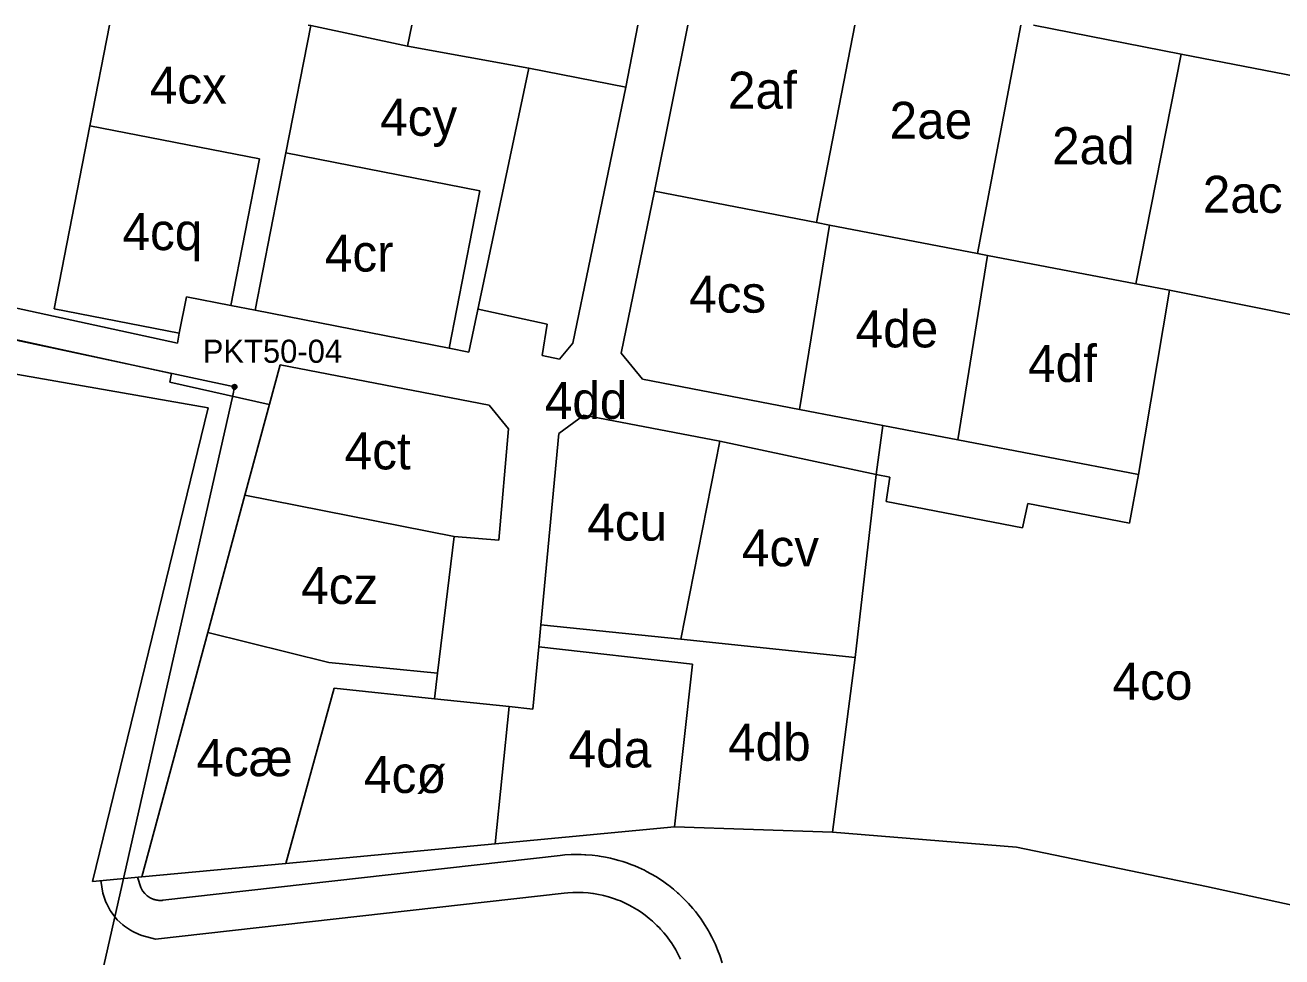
# Model space of a CAD drawing. Extents: x 702630 to 703245, y 6205279 to 6205714.
# Drawn here: x 702766.1 to 702969.7, y 6205559 to 6205710 of the extents above; entities that cross this region are included whole.
import ezdxf

# ---------------------------------------------------------------- set-up
doc = ezdxf.new("R2010")
doc.units = 0
for name, color, linetype in [('Matrikelnummer', 7, 'Continuous'), ('Matrikelnummer punkt', 7, 'Continuous'), ('Matrikelskel Almindeligt', 7, 'Continuous'), ('Matrikelskel Vej', 7, 'Continuous'), ('Optaget vej', 7, 'Continuous'), ('Punkt', 7, 'Continuous'), ('Punkt_Text', 7, 'Continuous'), ('Trykledning', 7, 'Continuous')]:
    doc.layers.add(name, color=color, linetype=linetype)

msp = doc.modelspace()

# ---------------------------------------------------------------- linework, layer by layer
at = {"layer": 'Matrikelnummer punkt'}
for p, q in [((702790.96, 6205700.28), (702790.96, 6205700.28)), ((702884.4, 6205699.46), (702884.4, 6205699.46)), ((702828.34, 6205695.07), (702828.34, 6205695.07)), ((702910.94, 6205694.58), (702910.94, 6205694.58)), ((702937.47, 6205690.46), (702937.47, 6205690.46)), ((702961.65, 6205682.59), (702961.65, 6205682.59)), ((702786.56, 6205676.54), (702786.56, 6205676.54)), ((702818.97, 6205673.07), (702818.97, 6205673.07)), ((702878.18, 6205666.41), (702878.18, 6205666.41)), ((702905.44, 6205660.78), (702905.44, 6205660.78)), ((702933.03, 6205655.18), (702933.03, 6205655.18)), ((702855.27, 6205649.19), (702855.27, 6205649.19)), ((702821.9, 6205641.01), (702821.9, 6205641.01)), ((702861.9, 6205629.48), (702861.9, 6205629.48)), ((702887, 6205625.31), (702887, 6205625.31)), ((702815.37, 6205619.21), (702815.37, 6205619.21)), ((702946.93, 6205603.68), (702946.93, 6205603.68)), ((702884.81, 6205593.8), (702884.81, 6205593.8)), ((702858.94, 6205592.72), (702858.94, 6205592.72)), ((702799.44, 6205591.3), (702799.44, 6205591.3)), ((702825.76, 6205588.58), (702825.76, 6205588.58))]:
    msp.add_line(p, q, dxfattribs=at)
at = {"layer": 'Matrikelskel Almindeligt'}
for p, q in [((702779.79, 6205710), (702776.6, 6205693.68)), ((702808.36, 6205689.31), (702812.39, 6205709.92)), ((702811.96, 6205710), (702812.39, 6205709.92)), ((702812.39, 6205709.92), (702828.07, 6205706.6)), ((702828.07, 6205706.6), (702828.73, 6205710)), ((702900.53, 6205710), (702894.35, 6205678.01)), ((702927.44, 6205710), (702920.44, 6205672.99)), ((702828.07, 6205706.6), (702847.72, 6205703.01)), ((702953.4, 6205705.3), (702946.08, 6205668.07)), ((702847.72, 6205703.01), (702838.02, 6205657.02)), ((702847.72, 6205703.01), (702863.43, 6205699.94)), ((702770.81, 6205664.04), (702776.6, 6205693.68)), ((702776.6, 6205693.68), (702804.09, 6205688.31)), ((702808.36, 6205689.31), (702803.37, 6205663.79)), ((702839.77, 6205683.17), (702808.36, 6205689.31)), ((702804.09, 6205688.31), (702799.45, 6205664.56)), ((702834.78, 6205657.65), (702839.77, 6205683.17)), ((702894.35, 6205678.01), (702868.1, 6205683.08)), ((702896.45, 6205677.61), (702891.6, 6205647.72)), ((702896.45, 6205677.61), (702894.35, 6205678.01)), ((702920.44, 6205672.99), (702896.45, 6205677.61)), ((702922.05, 6205672.68), (702920.44, 6205672.99)), ((702922.05, 6205672.68), (702917.22, 6205642.79)), ((702946.08, 6205668.07), (702922.05, 6205672.68)), ((702951.51, 6205667.04), (702946.08, 6205668.07)), ((702946.52, 6205637.17), (702951.51, 6205667.04)), ((702980.12, 6205661.33), (702951.51, 6205667.04)), ((702770.81, 6205664.04), (702791.08, 6205660.08)), ((702748.87, 6205656.2), (702795.76, 6205648)), ((702801.71, 6205633.81), (702807.42, 6205654.96)), ((702795.76, 6205648), (702777, 6205571.25)), ((702878.66, 6205642.57), (702872.33, 6205610.52)), ((702904, 6205637.18), (702900.62, 6205607.54)), ((702795.7, 6205611.57), (702801.71, 6205633.81)), ((702801.71, 6205633.81), (702835.61, 6205627.16)), ((702872.33, 6205610.52), (702849.66, 6205612.81)), ((702785.01, 6205571.99), (702795.7, 6205611.57)), ((702815.29, 6205606.72), (702795.7, 6205611.57)), ((702900.62, 6205607.54), (702872.33, 6205610.52)), ((702849.33, 6205609.28), (702874.25, 6205606.46)), ((702832.92, 6205604.97), (702815.29, 6205606.72)), ((702874.25, 6205606.46), (702871.34, 6205580.08)), ((702896.93, 6205579.22), (702900.62, 6205607.54)), ((702816.18, 6205602.55), (702808.33, 6205574.16)), ((702832.42, 6205600.84), (702816.18, 6205602.55)), ((702844.53, 6205599.57), (702842.25, 6205577.33)), ((702842.25, 6205577.33), (702871.34, 6205580.08)), ((702871.34, 6205580.08), (702896.93, 6205579.22)), ((702896.93, 6205579.22), (702926.75, 6205576.82)), ((702808.33, 6205574.16), (702842.25, 6205577.33)), ((702926.75, 6205576.82), (702957.55, 6205570.41)), ((702785.01, 6205571.99), (702808.33, 6205574.16)), ((702785.01, 6205571.99), (702777, 6205571.25)), ((702957.55, 6205570.41), (702997.74, 6205561.71))]:
    msp.add_line(p, q, dxfattribs=at)
at = {"layer": 'Matrikelskel Vej'}
for p, q in [((702863.43, 6205699.94), (702865.37, 6205710)), ((702873.48, 6205710), (702868.1, 6205683.08)), ((702929.5, 6205710), (702953.4, 6205705.3)), ((702953.4, 6205705.3), (702972.11, 6205701.65)), ((702868.1, 6205683.08), (702862.66, 6205656.85)), ((702792.23, 6205665.97), (702791.08, 6205660.08)), ((702799.45, 6205664.56), (702792.23, 6205665.97)), ((702799.45, 6205664.56), (702803.37, 6205663.79)), ((702803.37, 6205663.79), (702834.78, 6205657.65)), ((702838.02, 6205657.02), (702834.78, 6205657.65)), ((702862.66, 6205656.85), (702866.15, 6205652.64)), ((702807.42, 6205654.96), (702841.3, 6205648.43)), ((702866.15, 6205652.64), (702891.6, 6205647.72)), ((702841.3, 6205648.43), (702844.41, 6205644.59)), ((702852.55, 6205643.84), (702856.62, 6205646.79)), ((702856.62, 6205646.79), (702878.66, 6205642.57)), ((702891.6, 6205647.72), (702905.06, 6205645.13)), ((702844.41, 6205644.59), (702842.86, 6205626.57)), ((702904, 6205637.18), (702905.06, 6205645.13)), ((702905.06, 6205645.13), (702917.22, 6205642.79)), ((702849.66, 6205612.81), (702852.55, 6205643.84)), ((702878.66, 6205642.57), (702904, 6205637.18)), ((702917.22, 6205642.79), (702946.52, 6205637.17)), ((702835.61, 6205627.16), (702832.92, 6205604.97)), ((702842.86, 6205626.57), (702835.61, 6205627.16)), ((702849.33, 6205609.28), (702849.66, 6205612.81)), ((702848.39, 6205599.16), (702849.33, 6205609.28)), ((702832.92, 6205604.97), (702832.42, 6205600.84)), ((702832.42, 6205600.84), (702844.53, 6205599.57)), ((702844.53, 6205599.57), (702848.39, 6205599.16))]:
    msp.add_line(p, q, dxfattribs=at)
at = {"layer": 'Optaget vej'}
for p, q in [((702863.43, 6205699.94), (702854.82, 6205658.47)), ((702790.77, 6205658.47), (702751, 6205667.12)), ((702850.71, 6205661.57), (702839.53, 6205663.96)), ((702789.81, 6205653.57), (702750.05, 6205662.21)), ((702849.86, 6205656.46), (702850.71, 6205661.57)), ((702791.08, 6205660.08), (702790.77, 6205658.47)), ((702854.82, 6205658.47), (702852.68, 6205655.9)), ((702852.68, 6205655.9), (702849.86, 6205656.46)), ((702789.81, 6205653.57), (702789.53, 6205652.13)), ((702789.53, 6205652.13), (702805.63, 6205648.55)), ((702906.22, 6205636.75), (702904, 6205637.18)), ((702905.64, 6205632.79), (702906.22, 6205636.75)), ((702946.52, 6205637.17), (702945.07, 6205629.3)), ((702927.71, 6205628.55), (702905.64, 6205632.79)), ((702928.55, 6205632.46), (702927.71, 6205628.55)), ((702928.55, 6205632.46), (702945.07, 6205629.3)), ((702784.29, 6205571.92), (702784.86, 6205570.25)), ((702784.86, 6205570.25), (702785.12, 6205569.75)), ((702785.12, 6205569.75), (702785.47, 6205569.3)), ((702785.47, 6205569.3), (702785.88, 6205568.92)), ((702785.88, 6205568.92), (702786.35, 6205568.6)), ((702786.35, 6205568.6), (702786.93, 6205568.34)), ((702787.2, 6205561.87), (702785.03, 6205562.5))]:
    msp.add_line(p, q, dxfattribs=at)
for points in [[(702786.93, 6205568.34), (702787.08, 6205568.3), (702787.09, 6205568.3), (702787.1, 6205568.29), (702787.11, 6205568.29), (702787.12, 6205568.29), (702787.12, 6205568.29), (702787.13, 6205568.29), (702787.13, 6205568.28), (702787.14, 6205568.28), (702787.17, 6205568.27), (702787.18, 6205568.27), (702787.23, 6205568.26), (702787.24, 6205568.26), (702787.24, 6205568.26), (702787.3, 6205568.25), (702787.32, 6205568.24), (702787.36, 6205568.23), (702787.39, 6205568.23), (702787.44, 6205568.22), (702787.5, 6205568.21), (702787.53, 6205568.2), (702787.57, 6205568.2), (702787.66, 6205568.19), (702787.71, 6205568.18), (702787.76, 6205568.18), (702787.78, 6205568.18), (702787.84, 6205568.17), (702787.86, 6205568.17), (702787.86, 6205568.17), (702787.96, 6205568.17), (702788.11, 6205568.17), (702788.12, 6205568.17), (702788.15, 6205568.17), (702788.23, 6205568.18), (702788.28, 6205568.18), (702788.39, 6205568.19), (702788.42, 6205568.19), (702852.8, 6205575.47), (702853.53, 6205575.54), (702854.56, 6205575.6), (702854.86, 6205575.61), (702855.71, 6205575.62), (702856.22, 6205575.61), (702856.81, 6205575.58), (702856.95, 6205575.58), (702857.96, 6205575.5), (702858.89, 6205575.38), (702859.13, 6205575.35), (702860.15, 6205575.17), (702860.94, 6205575.01), (702861.31, 6205574.92), (702862.31, 6205574.66), (702862.95, 6205574.46), (702863.44, 6205574.3), (702864.41, 6205573.95), (702864.91, 6205573.75), (702865.51, 6205573.49), (702866.44, 6205573.05), (702866.8, 6205572.87), (702867.49, 6205572.49), (702868.39, 6205571.97), (702868.61, 6205571.83), (702869.38, 6205571.32), (702870.22, 6205570.72), (702870.33, 6205570.64), (702871.14, 6205569.99), (702871.83, 6205569.4), (702872.04, 6205569.22), (702872.79, 6205568.5), (702873.33, 6205567.95), (702873.61, 6205567.65), (702874.29, 6205566.87), (702874.7, 6205566.37), (702875.03, 6205565.95), (702875.64, 6205565.11), (702875.93, 6205564.69), (702876.3, 6205564.12), (702876.83, 6205563.23), (702877.01, 6205562.9), (702877.39, 6205562.19), (702877.84, 6205561.25), (702877.94, 6205561.03), (702878.31, 6205560.17), (702878.66, 6205559.22), (702878.71, 6205559.06), (702879.03, 6205558.08)], [(702778.35, 6205571.38), (702778.69, 6205569.35), (702778.73, 6205569.21), (702779.17, 6205567.89), (702779.26, 6205567.7), (702779.88, 6205566.53), (702780.03, 6205566.3), (702780.8, 6205565.29), (702781.02, 6205565.05), (702781.91, 6205564.22), (702782.21, 6205563.98), (702783.17, 6205563.34), (702783.56, 6205563.12), (702784.56, 6205562.67), (702785.03, 6205562.5)], [(702787.2, 6205561.87), (702853.44, 6205569.36), (702854.01, 6205569.42), (702854.84, 6205569.46), (702854.99, 6205569.47), (702855.68, 6205569.48), (702856.04, 6205569.47), (702856.52, 6205569.45), (702856.54, 6205569.45), (702857.35, 6205569.38), (702858.08, 6205569.29), (702858.18, 6205569.28), (702859, 6205569.14), (702859.6, 6205569.01), (702859.82, 6205568.96), (702860.63, 6205568.75), (702861.1, 6205568.61), (702861.43, 6205568.5), (702862.21, 6205568.21), (702862.55, 6205568.08), (702862.98, 6205567.89), (702863.74, 6205567.53), (702863.96, 6205567.42), (702864.48, 6205567.14), (702865.2, 6205566.72), (702865.3, 6205566.65), (702865.9, 6205566.26), (702866.58, 6205565.77), (702866.58, 6205565.77), (702867.24, 6205565.25), (702867.78, 6205564.79), (702867.87, 6205564.71), (702868.48, 6205564.13), (702868.89, 6205563.71), (702869.06, 6205563.53), (702869.61, 6205562.9), (702869.9, 6205562.54), (702870.13, 6205562.25), (702870.62, 6205561.57), (702870.82, 6205561.29), (702871.08, 6205560.87), (702871.52, 6205560.16), (702871.62, 6205559.97), (702871.91, 6205559.42), (702872.27, 6205558.66)]]:
    msp.add_lwpolyline(points, dxfattribs=at)
at = {"layer": 'Punkt'}
msp.add_line((702800.04, 6205651.38), (702800.04, 6205651.38), dxfattribs=at)
for radius in [0.375, 0.3, 0.225, 0.15, 0.075]:
    msp.add_circle((702800.04, 6205651.38), radius, dxfattribs=at)
at = {"layer": 'Trykledning'}
for points in [[(702745.65, 6205663.03), (702800.04, 6205651.38)], [(702800.04, 6205651.38), (702799.73, 6205649.98), (702770.2, 6205519.44), (702768.06, 6205511.77)]]:
    msp.add_lwpolyline(points, dxfattribs=at)

# ---------------------------------------------------------------- texts
at = {"layer": 'Matrikelnummer'}
for s, p in [('4cx', (702786.29, 6205697.28)), ('2af', (702879.98, 6205696.46)), ('4cy', (702823.62, 6205692.07)), ('2ae', (702906.17, 6205691.58)), ('2ad', (702932.5, 6205687.46)), ('2ac', (702956.92, 6205679.59)), ('4cq', (702781.87, 6205673.54)), ('4cr', (702814.66, 6205670.07)), ('4cs', (702873.69, 6205663.41)), ('4de', (702900.67, 6205657.78)), ('4df', (702928.61, 6205652.18)), ('4dd', (702850.3, 6205646.19)), ('4ct', (702817.87, 6205638.01)), ('4cu', (702857.19, 6205626.48)), ('4cv', (702882.25, 6205622.31)), ('4cz', (702810.82, 6205616.21)), ('4co', (702942.31, 6205600.68)), ('4da', (702854.16, 6205589.72)), ('4db', (702880, 6205590.8)), ('4cæ', (702793.85, 6205588.3)), ('4cø', (702821.01, 6205585.58))]:
    msp.add_text(s, height=6, dxfattribs=at).set_placement(p)
at = {"layer": 'Punkt_Text'}
msp.add_text('PKT50-04', height=3.75, dxfattribs=at).set_placement((702794.88, 6205655.28))

doc.saveas('drawing.dxf')
